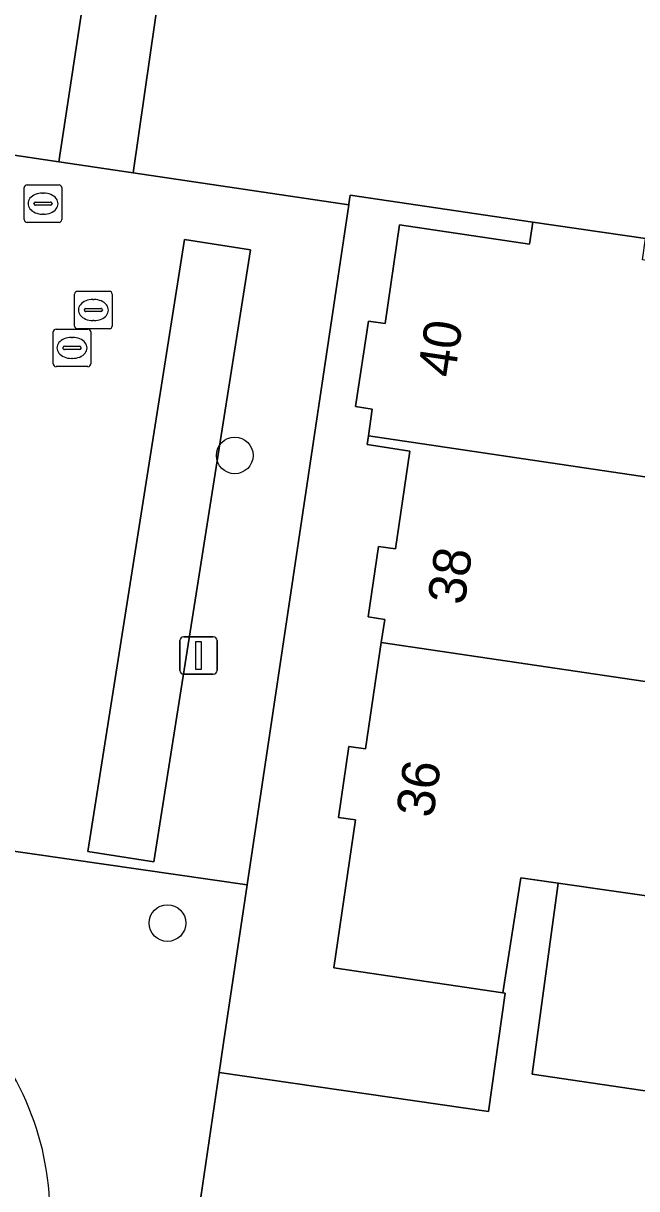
# Model space of a CAD drawing. Extents: x 164148 to 165261, y 382513 to 383432.
# Drawn here: x 164286.53 to 164302.89, y 383022.81 to 383053.88 of the extents above; entities that cross this region are included whole.
import ezdxf

# ---------------------------------------------------------------- set-up
doc = ezdxf.new("R2010")
doc.units = 0
for name, color, linetype in [('IMGEO_Boom', 7, 'Continuous'), ('IMGEO_Erf', 7, 'Continuous'), ('IMGEO_Fietspad_open', 7, 'Continuous'), ('IMGEO_Groenvoorziening', 7, 'Continuous'), ('IMGEO_Kolk', 7, 'Continuous'), ('IMGEO_Lichtmast', 7, 'Continuous'), ('IMGEO_Pand', 7, 'Continuous'), ('IMGEO_Pand_nummerreeks', 7, 'Continuous'), ('IMGEO_Parkeervlak_open', 7, 'Continuous'), ('IMGEO_Rijbaan_lokaal_open', 7, 'Continuous'), ('IMGEO_Rioolput', 7, 'Continuous'), ('IMGEO_Voetpad_open', 7, 'Continuous')]:
    doc.layers.add(name, color=color, linetype=linetype)

msp = doc.modelspace()

# ---------------------------------------------------------------- linework, layer by layer
at = {"layer": 'IMGEO_Boom'}
for centre in [(164292.167, 383042.363), (164290.373, 383029.895)]:
    msp.add_circle(centre, 0.489, dxfattribs=at)
at = {"layer": 'IMGEO_Erf'}
msp.add_lwpolyline([(164296.836, 383042.481), (164295.7, 383042.656), (164295.733, 383042.883), (164295.837, 383043.599), (164295.391, 383043.672), (164295.731, 383045.946), (164296.177, 383045.881), (164296.564, 383048.51), (164300.031, 383047.992), (164300.119, 383048.586), (164295.247, 383049.303), (164295.212, 383049.069), (164295.209, 383049.046), (164292.499, 383030.912), (164291.869, 383026.7), (164291.752, 383025.908), (164298.938, 383024.873), (164299.384, 383028.026), (164299.322, 383028.035), (164294.809, 383028.701), (164295.384, 383032.651), (164294.933, 383032.712), (164295.214, 383034.603), (164295.659, 383034.543), (164296.077, 383037.373), (164296.168, 383037.992), (164295.726, 383038.056), (164295.998, 383039.935), (164296.453, 383039.873)], close=True, dxfattribs=at)
at = {"layer": 'IMGEO_Fietspad_open'}
msp.add_lwpolyline([(164290.642, 383058.11), (164290.645, 383058.127), (164291.001, 383060.584), (164289.109, 383060.95), (164287.476, 383050.195), (164289.455, 383049.901)], close=True, dxfattribs=at)
at = {"layer": 'IMGEO_Groenvoorziening'}
for points in [[(164235.932, 383066.495), (164235.668, 383064.759), (164234.719, 383058.116), (164239.598, 383057.474), (164242.559, 383057.041), (164274.02, 383052.369), (164276.924, 383051.954), (164276.836, 383051.335), (164280.394, 383050.839), (164280.45, 383051.24), (164281.812, 383051.037), (164287.476, 383050.195), (164289.109, 383060.95), (164241.04, 383067.994), (164239.423, 383068.201), (164236.742, 383068.586), (164236.531, 383068.621)], [(164349.332, 383049.355), (164349.656, 383051.856), (164291.001, 383060.584), (164290.645, 383058.127), (164290.642, 383058.11), (164289.455, 383049.901), (164295.209, 383049.046), (164295.212, 383049.069), (164295.247, 383049.303), (164300.119, 383048.586), (164303.121, 383048.144), (164316.052, 383046.228), (164321.502, 383045.42), (164333.125, 383043.698), (164334.498, 383043.494), (164337.518, 383043.057), (164342.452, 383042.342), (164342.411, 383042.068), (164348.276, 383041.192)]]:
    msp.add_lwpolyline(points, close=True, dxfattribs=at)
at = {"layer": 'IMGEO_Kolk'}
for p, q in [((164287.326, 383044.804), (164287.326, 383045.656)), ((164287.401, 383045.73), (164288.253, 383045.73)), ((164288.327, 383045.656), (164288.327, 383044.804)), ((164287.628, 383045.273), (164288.026, 383045.273)), ((164287.814, 383045.51), (164287.839, 383045.51)), ((164287.585, 383045.224), (164287.585, 383045.236)), ((164288.023, 383045.187), (164287.625, 383045.187)), ((164287.837, 383044.95), (164287.812, 383044.95)), ((164288.069, 383045.236), (164288.069, 383045.224)), ((164288.253, 383044.73), (164287.401, 383044.73))]:
    msp.add_line(p, q, dxfattribs=at)
for points in [[(164287.326, 383044.804), (164287.326, 383045.656)], [(164287.401, 383045.73), (164288.253, 383045.73)], [(164288.327, 383045.656), (164288.327, 383044.804)], [(164288.253, 383044.73), (164287.401, 383044.73)]]:
    msp.add_lwpolyline(points, dxfattribs=at)
for centre, radius, start, end in [((164287.403, 383045.654), 0.0765, 91.552, 178.448), ((164287.403, 383045.654), 0.0765, 91.552, 178.448), ((164288.251, 383045.654), 0.0765, 1.552, 88.448), ((164288.251, 383045.654), 0.0765, 1.552, 88.448), ((164287.625, 383045.233), 0.0403, 85.8775, 175.7526), ((164288.03, 383045.235), 0.0386, 1.7309, 96.639), ((164287.622, 383045.223), 0.0366, 178.938, 274.7102), ((164288.026, 383045.23), 0.043, 264.8664, 352.4533), ((164287.403, 383044.806), 0.0765, 181.552, 268.448), ((164287.403, 383044.806), 0.0765, 181.552, 268.448), ((164288.251, 383044.806), 0.0765, 271.552, 358.448), ((164288.251, 383044.806), 0.0765, 271.552, 358.448)]:
    msp.add_arc(centre, radius, start, end, dxfattribs=at)
for centre, major_axis, ratio, start_param, end_param in [((164287.813, 383045.23), (-0.387, 0.002), 0.722429, 4.712389, 7.853982), ((164287.838, 383045.23), (-0.39, 0.002), 0.717154, 1.570796, 4.712389)]:
    msp.add_ellipse(centre, major_axis=major_axis, ratio=ratio, start_param=start_param, end_param=end_param, dxfattribs=at)
at = {"layer": 'IMGEO_Lichtmast'}
for p, q in [((164290.806, 383037.528), (164291.596, 383037.528)), ((164291.596, 383037.528), (164290.806, 383037.528)), ((164290.706, 383036.628), (164290.706, 383037.428)), ((164290.706, 383037.428), (164290.706, 383036.628)), ((164291.696, 383037.428), (164291.696, 383036.628)), ((164291.696, 383036.628), (164291.696, 383037.428)), ((164291.596, 383036.528), (164290.806, 383036.528)), ((164290.806, 383036.528), (164291.596, 383036.528))]:
    msp.add_line(p, q, dxfattribs=at)
msp.add_lwpolyline([(164291.126, 383037.403), (164291.276, 383037.403), (164291.276, 383036.653), (164291.126, 383036.653), (164291.126, 383037.403)], dxfattribs=at)
for centre, start, end in [((164290.806, 383037.428), 90, 180), ((164290.806, 383037.428), 90, 180), ((164291.596, 383037.428), 0, 90), ((164291.596, 383037.428), 360, 90), ((164290.806, 383036.628), 180, 270), ((164290.806, 383036.628), 180, 270), ((164291.596, 383036.628), 270, 0), ((164291.596, 383036.628), 270, 0)]:
    msp.add_arc(centre, 0.1, start, end, dxfattribs=at)
at = {"layer": 'IMGEO_Pand'}
for points in [[(164309.335, 383046.613), (164303.045, 383047.574), (164303.121, 383048.144), (164300.119, 383048.586), (164300.031, 383047.992), (164296.564, 383048.51), (164296.177, 383045.881), (164295.731, 383045.946), (164295.391, 383043.672), (164295.837, 383043.599), (164295.733, 383042.883), (164308.499, 383040.995)], [(164308.463, 383040.753), (164308.499, 383040.995), (164295.733, 383042.883), (164295.7, 383042.656), (164296.836, 383042.481), (164296.453, 383039.873), (164295.998, 383039.935), (164295.726, 383038.056), (164296.168, 383037.992), (164296.077, 383037.373), (164307.743, 383035.648), (164307.778, 383035.881), (164305.408, 383036.233), (164306.09, 383041.105)], [(164307.743, 383035.648), (164296.077, 383037.373), (164295.659, 383034.543), (164295.214, 383034.603), (164294.933, 383032.712), (164295.384, 383032.651), (164294.809, 383028.701), (164299.322, 383028.035), (164299.794, 383031.104), (164300.796, 383030.959), (164306.916, 383030.074)]]:
    msp.add_lwpolyline(points, close=True, dxfattribs=at)
at = {"layer": 'IMGEO_Parkeervlak_open'}
for points in [[(164290.009, 383031.53), (164292.587, 383047.843), (164290.83, 383048.121), (164288.253, 383031.807)], [(164315.481, 383028.705), (164306.902, 383029.983), (164306.916, 383030.074), (164300.796, 383030.959), (164300.1, 383025.87), (164314.732, 383023.702)]]:
    msp.add_lwpolyline(points, close=True, dxfattribs=at)
at = {"layer": 'IMGEO_Rijbaan_lokaal_open'}
msp.add_lwpolyline([(164314.732, 383023.702), (164300.1, 383025.87), (164300.796, 383030.959), (164299.794, 383031.104), (164299.322, 383028.035), (164299.384, 383028.026), (164298.938, 383024.873), (164291.752, 383025.908), (164291.171, 383021.984), (164298.342, 383020.927), (164297.837, 383017.767), (164297.786, 383017.774), (164297.334, 383014.687), (164298.327, 383014.538), (164299.126, 383019.608), (164313.785, 383017.446)], dxfattribs=at)
at = {"layer": 'IMGEO_Rioolput'}
for p, q in [((164286.554, 383048.651), (164286.554, 383049.503)), ((164286.629, 383049.577), (164287.481, 383049.577)), ((164287.042, 383049.357), (164287.067, 383049.357)), ((164287.555, 383049.503), (164287.555, 383048.651)), ((164286.813, 383049.071), (164286.813, 383049.083)), ((164287.251, 383049.034), (164286.853, 383049.034)), ((164286.856, 383049.12), (164287.254, 383049.12)), ((164287.297, 383049.083), (164287.297, 383049.071)), ((164287.065, 383048.797), (164287.04, 383048.797)), ((164287.481, 383048.577), (164286.629, 383048.577)), ((164287.897, 383045.814), (164287.897, 383046.666)), ((164287.972, 383046.74), (164288.824, 383046.74)), ((164288.385, 383046.52), (164288.41, 383046.52)), ((164288.898, 383046.666), (164288.898, 383045.814)), ((164288.156, 383046.234), (164288.156, 383046.246)), ((164288.594, 383046.197), (164288.196, 383046.197)), ((164288.199, 383046.283), (164288.597, 383046.283)), ((164288.64, 383046.246), (164288.64, 383046.234)), ((164288.408, 383045.96), (164288.383, 383045.96)), ((164288.824, 383045.74), (164287.972, 383045.74))]:
    msp.add_line(p, q, dxfattribs=at)
for points in [[(164286.554, 383048.651), (164286.554, 383049.503)], [(164286.629, 383049.577), (164287.481, 383049.577)], [(164287.555, 383049.503), (164287.555, 383048.651)], [(164287.481, 383048.577), (164286.629, 383048.577)], [(164287.897, 383045.814), (164287.897, 383046.666)], [(164287.972, 383046.74), (164288.824, 383046.74)], [(164288.898, 383046.666), (164288.898, 383045.814)], [(164288.824, 383045.74), (164287.972, 383045.74)]]:
    msp.add_lwpolyline(points, dxfattribs=at)
for centre, radius, start, end in [((164286.631, 383049.501), 0.0765, 91.552, 178.448), ((164286.631, 383049.501), 0.0765, 91.552, 178.448), ((164287.479, 383049.501), 0.0765, 1.552, 88.448), ((164287.479, 383049.501), 0.0765, 1.552, 88.448), ((164286.853, 383049.08), 0.0403, 85.8775, 175.7526), ((164286.85, 383049.07), 0.0366, 178.938, 274.7102), ((164287.254, 383049.077), 0.043, 264.8664, 352.4533), ((164287.258, 383049.082), 0.0386, 1.7309, 96.639), ((164286.631, 383048.653), 0.0765, 181.552, 268.448), ((164286.631, 383048.653), 0.0765, 181.552, 268.448), ((164287.479, 383048.653), 0.0765, 271.552, 358.448), ((164287.479, 383048.653), 0.0765, 271.552, 358.448), ((164287.974, 383046.664), 0.0765, 91.552, 178.448), ((164287.974, 383046.664), 0.0765, 91.552, 178.448), ((164288.822, 383046.664), 0.0765, 1.552, 88.448), ((164288.822, 383046.664), 0.0765, 1.552, 88.448), ((164288.196, 383046.243), 0.0403, 85.8775, 175.7526), ((164288.193, 383046.233), 0.0366, 178.938, 274.7102), ((164288.597, 383046.24), 0.043, 264.8664, 352.4533), ((164288.601, 383046.245), 0.0386, 1.7309, 96.639), ((164287.974, 383045.816), 0.0765, 181.552, 268.448), ((164287.974, 383045.816), 0.0765, 181.552, 268.448), ((164288.822, 383045.816), 0.0765, 271.552, 358.448), ((164288.822, 383045.816), 0.0765, 271.552, 358.448)]:
    msp.add_arc(centre, radius, start, end, dxfattribs=at)
for centre, major_axis, ratio, start_param, end_param in [((164287.041, 383049.077), (-0.387, 0.002), 0.722429, 4.712389, 7.853982), ((164287.066, 383049.077), (-0.39, 0.002), 0.717154, 1.570796, 4.712389), ((164288.384, 383046.24), (-0.387, 0.002), 0.722429, 4.712389, 7.853982), ((164288.409, 383046.24), (-0.39, 0.002), 0.717154, 1.570796, 4.712389)]:
    msp.add_ellipse(centre, major_axis=major_axis, ratio=ratio, start_param=start_param, end_param=end_param, dxfattribs=at)
at = {"layer": 'IMGEO_Voetpad_open'}
for points in [[(164295.209, 383049.046), (164289.455, 383049.901), (164287.476, 383050.195), (164281.812, 383051.037), (164279.108, 383032.842), (164292.499, 383030.912)], [(164290.83, 383048.121), (164292.587, 383047.843), (164290.009, 383031.53), (164288.253, 383031.807)]]:
    msp.add_lwpolyline(points, close=True, dxfattribs=at)
msp.add_lwpolyline([(164277.599, 382930.234), (164278.188, 382934.213), (164291.171, 383021.984), (164291.752, 383025.908), (164291.869, 383026.7), (164292.499, 383030.912), (164279.108, 383032.842), (164276.628, 383033.326), (164267.895, 383034.634), (164259.465, 383035.864), (164256.481, 383036.306), (164254.721, 383036.566), (164251.734, 383037.008), (164243.28, 383038.25), (164234.568, 383039.547), (164232.031, 383039.843), (164231.418, 383035.873), (164232.471, 383035.679), (164233.544, 383035.52)], dxfattribs=at)
msp.add_arc((164279.747, 383022.131), 7.49, 347.8515, 83.7329, dxfattribs=at)
msp.add_arc((164279.747, 383022.131), 7.49, 347.8515, 83.7329, dxfattribs=at)

# ---------------------------------------------------------------- texts
at = {"layer": 'IMGEO_Pand_nummerreeks'}
for s, rotation, p in [('40', 81.4975, (164298.029, 383044.412)), ('38', 81.7611, (164298.294, 383038.352)), ('36', 81.5491, (164297.455, 383032.675))]:
    msp.add_text(s, height=1, rotation=rotation, dxfattribs=at).set_placement(p)

doc.saveas('drawing.dxf')
